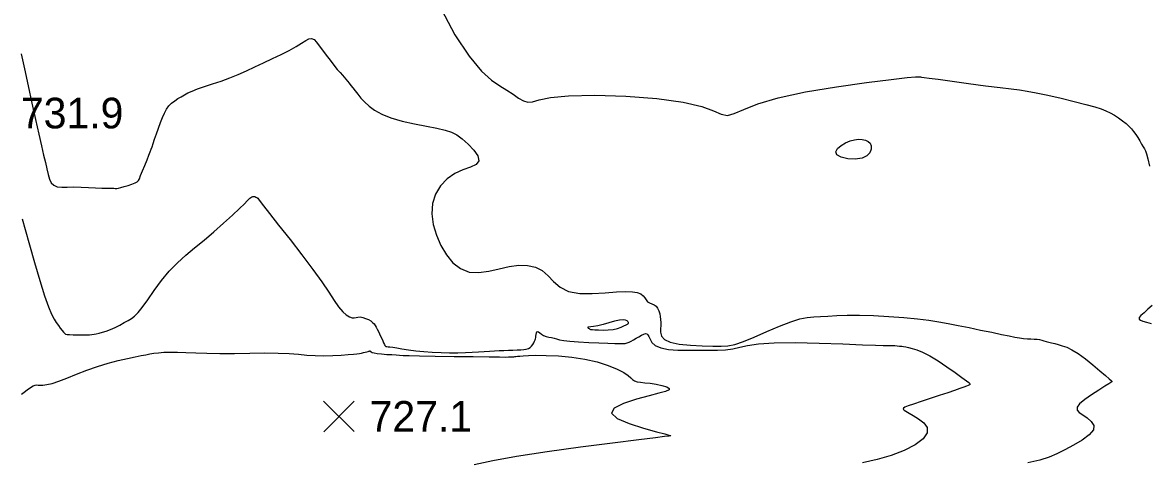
# Model space of a CAD drawing. Extents: x 2566142 to 2571431, y 418755 to 421584.
# Drawn here: x 2569092 to 2569643, y 420845 to 421060 of the extents above; entities that cross this region are included whole.
import ezdxf

# ---------------------------------------------------------------- set-up
doc = ezdxf.new("R2010")
doc.units = 0
for name, color, linetype in [('Contour_ADS_Major', 7, 'Continuous'), ('Contour_ADS_Minor', 7, 'Continuous'), ('Contour_ADS_Spot_Elevation', 7, 'Continuous')]:
    doc.layers.add(name, color=color, linetype=linetype)

# ---------------------------------------------------------------- blocks, each defined once
blk = doc.blocks.new('S750')
at = {"layer": 'Contour_ADS_Spot_Elevation'}
for p, q in [((-0.5, 0.498), (0.5, -0.498)), ((-0.498, -0.5), (0.498, 0.5))]:
    blk.add_line(p, q, dxfattribs=at)

msp = doc.modelspace()

# ---------------------------------------------------------------- linework, layer by layer
at = {"layer": 'Contour_ADS_Major'}
for points in [[(2569126.55, 420907.84), (2569127.66, 420908.08), (2569129.03, 420908.39), (2569130.67, 420908.82), (2569132.55, 420909.41), (2569134.63, 420910.2), (2569136.87, 420911.21), (2569139.15, 420912.36), (2569141.33, 420913.53), (2569143.27, 420914.62), (2569144.91, 420915.59), (2569146.43, 420916.72), (2569148.1, 420918.41), (2569150.17, 420921), (2569152.83, 420924.74), (2569156.01, 420929.27), (2569159.58, 420934.09), (2569163.39, 420938.72), (2569167.35, 420942.8), (2569171.46, 420946.48), (2569175.79, 420950.05), (2569180.39, 420953.83), (2569185.23, 420957.97), (2569189.99, 420962.21), (2569194.31, 420966.16), (2569197.78, 420969.4), (2569200.14, 420971.66), (2569201.58, 420973.08), (2569202.39, 420973.91), (2569202.89, 420974.4), (2569203.33, 420974.76), (2569203.77, 420975.02), (2569204.23, 420975.18), (2569204.72, 420975.22), (2569205.25, 420975.15), (2569205.8, 420974.97), (2569206.31, 420974.7), (2569206.74, 420974.35), (2569207.13, 420973.87), (2569207.88, 420972.8), (2569209.47, 420970.65), (2569212.39, 420966.87), (2569216.92, 420961.18), (2569222.49, 420954.19), (2569228.35, 420946.7), (2569233.74, 420939.56), (2569238.07, 420933.42), (2569241.43, 420928.37), (2569244.09, 420924.31), (2569246.3, 420921.18), (2569248.28, 420918.89), (2569250.06, 420917.32), (2569251.61, 420916.37), (2569252.9, 420915.93), (2569253.95, 420915.87), (2569254.85, 420916.03), (2569255.76, 420916.24), (2569256.8, 420916.3), (2569258.07, 420916.08), (2569259.46, 420915.63), (2569260.84, 420915.03), (2569262.03, 420914.34), (2569262.95, 420913.65), (2569263.62, 420912.93), (2569264.16, 420912.15), (2569264.66, 420911.28), (2569265.18, 420910.31), (2569265.73, 420909.25), (2569266.29, 420908.11), (2569266.85, 420906.94), (2569267.38, 420905.75), (2569267.88, 420904.63), (2569268.32, 420903.64), (2569268.68, 420902.85), (2569268.95, 420902.33), (2569269.19, 420902.03), (2569269.48, 420901.87), (2569269.89, 420901.8), (2569270.5, 420901.73), (2569271.42, 420901.63), (2569272.78, 420901.46), (2569274.71, 420901.17), (2569277.28, 420900.76), (2569280.42, 420900.26), (2569284.03, 420899.76), (2569287.98, 420899.33), (2569292.16, 420899.04), (2569296.44, 420898.87), (2569300.65, 420898.8), (2569304.65, 420898.82), (2569308.33, 420898.9), (2569311.69, 420899.03), (2569314.76, 420899.19), (2569317.57, 420899.36), (2569320.17, 420899.54), (2569322.6, 420899.7), (2569324.92, 420899.85), (2569327.19, 420899.96), (2569329.44, 420900.04), (2569331.61, 420900.11), (2569333.63, 420900.17)], [(2569091.39, 420964.38), (2569092.8, 420959.06), (2569094.87, 420951.59), (2569097.34, 420942.89), (2569099.92, 420934.17), (2569102.29, 420926.63), (2569104.2, 420921.2), (2569105.72, 420917.59), (2569106.95, 420915.24), (2569108.03, 420913.57), (2569109.06, 420912.11), (2569110.02, 420910.81), (2569110.86, 420909.72), (2569111.53, 420908.87), (2569112.05, 420908.3), (2569112.58, 420907.95), (2569113.35, 420907.76), (2569114.58, 420907.65), (2569116.4, 420907.57), (2569118.59, 420907.51), (2569120.85, 420907.49), (2569122.84, 420907.5), (2569124.36, 420907.56), (2569125.52, 420907.67), (2569126.55, 420907.84)], [(2569333.63, 420900.17), (2569335.42, 420900.25), (2569336.93, 420900.38), (2569338.18, 420900.59), (2569339.21, 420900.92), (2569340.07, 420901.4), (2569340.79, 420902.06), (2569341.39, 420902.84), (2569341.86, 420903.65), (2569342.23, 420904.41), (2569342.48, 420905.08), (2569342.66, 420905.68), (2569342.78, 420906.28), (2569342.88, 420906.96), (2569342.99, 420907.73), (2569343.15, 420908.47), (2569343.37, 420909.04), (2569343.71, 420909.26), (2569344.18, 420909.05), (2569344.81, 420908.51), (2569345.63, 420907.84), (2569346.64, 420907.21), (2569347.85, 420906.75), (2569349.19, 420906.44), (2569350.55, 420906.19), (2569351.84, 420905.92), (2569353.03, 420905.58), (2569354.44, 420905.18), (2569356.47, 420904.77), (2569359.49, 420904.39), (2569363.74, 420904.07), (2569368.71, 420903.81), (2569373.74, 420903.6), (2569378.16, 420903.44), (2569381.47, 420903.32), (2569383.79, 420903.25), (2569385.4, 420903.27), (2569386.58, 420903.38), (2569387.58, 420903.61), (2569388.53, 420903.97), (2569389.52, 420904.47), (2569390.63, 420905.1), (2569391.92, 420905.85), (2569393.3, 420906.64), (2569394.62, 420907.36), (2569395.76, 420907.89), (2569396.61, 420908.15), (2569397.23, 420908.06), (2569397.72, 420907.6), (2569398.19, 420906.71), (2569398.76, 420905.4), (2569399.71, 420903.88), (2569401.34, 420902.39), (2569403.97, 420901.18), (2569407.77, 420900.44), (2569412.44, 420900.09), (2569417.55, 420899.98), (2569422.66, 420899.98), (2569427.41, 420899.99), (2569431.75, 420900.05), (2569435.69, 420900.27), (2569439.27, 420900.74), (2569442.64, 420901.5), (2569446.55, 420902.38), (2569451.86, 420903.19), (2569459.46, 420903.7), (2569469.8, 420903.78), (2569481.6, 420903.52), (2569493.15, 420903.11), (2569502.76, 420902.72), (2569509.16, 420902.49), (2569512.86, 420902.4), (2569514.83, 420902.39), (2569516.03, 420902.39), (2569517.23, 420902.35), (2569518.53, 420902.28), (2569519.8, 420902.18), (2569520.96, 420902.07), (2569521.95, 420901.95), (2569522.89, 420901.8), (2569523.95, 420901.61), (2569525.29, 420901.34), (2569527.06, 420900.94), (2569529.35, 420900.27), (2569532.21, 420899.14), (2569535.71, 420897.35), (2569539.81, 420894.84), (2569544.13, 420891.94), (2569548.18, 420889.07), (2569551.47, 420886.67), (2569553.64, 420885.08), (2569554.85, 420884.17), (2569555.36, 420883.71), (2569555.47, 420883.49), (2569555.4, 420883.32), (2569555.12, 420883.11), (2569554.56, 420882.84), (2569553.66, 420882.47), (2569552.32, 420881.96), (2569550.43, 420881.28), (2569547.88, 420880.4)], [(2569547.88, 420880.4), (2569544.53, 420879.26), (2569540.37, 420877.89), (2569535.83, 420876.4), (2569531.44, 420874.95), (2569527.73, 420873.72), (2569525.11, 420872.81), (2569523.52, 420872.16), (2569522.77, 420871.68), (2569522.68, 420871.26), (2569523.11, 420870.78), (2569524.05, 420870.17), (2569525.55, 420869.32), (2569527.64, 420868.13), (2569530.24, 420866.54), (2569532.74, 420864.57), (2569534.39, 420862.25), (2569534.47, 420859.63), (2569532.42, 420856.76), (2569528.49, 420853.83), (2569523.14, 420851.02), (2569516.79, 420848.53), (2569509.9, 420846.52), (2569502.82, 420844.95)]]:
    msp.add_lwpolyline(points, dxfattribs=at)
at = {"layer": 'Contour_ADS_Minor'}
for points in [[(2569296.63, 421066.69), (2569303.23, 421054.3), (2569310.23, 421043.83), (2569316.25, 421036.59), (2569321.19, 421032.08), (2569325.26, 421029.31), (2569328.7, 421027.3), (2569331.7, 421025.3), (2569334.36, 421023.41), (2569336.74, 421021.97), (2569338.93, 421021.3), (2569341.18, 421021.61), (2569344.47, 421022.56), (2569349.97, 421023.7), (2569358.85, 421024.55), (2569371.71, 421024.75), (2569386.86, 421024.27), (2569402.04, 421023.14), (2569414.99, 421021.43), (2569424.04, 421019.27), (2569429.83, 421017.11), (2569433.61, 421015.48), (2569436.6, 421014.92), (2569439.98, 421015.79), (2569444.68, 421017.82), (2569451.58, 421020.55), (2569461.54, 421023.53), (2569474.93, 421026.38), (2569490.07, 421028.9), (2569504.76, 421030.99), (2569516.81, 421032.51), (2569524.59, 421033.4)], [(2569162.01, 421017.96), (2569163.18, 421019.58), (2569164.54, 421020.94), (2569166.05, 421022.09), (2569167.63, 421023.1), (2569169.21, 421024.03), (2569170.78, 421024.94), (2569172.49, 421025.86), (2569174.56, 421026.83), (2569177.21, 421027.87), (2569180.58, 421029.01), (2569184.5, 421030.27), (2569188.72, 421031.67), (2569193, 421033.21), (2569197.16, 421034.91), (2569201.24, 421036.73), (2569205.32, 421038.66), (2569209.51, 421040.67), (2569213.85, 421042.71), (2569218.13, 421044.74), (2569222.1, 421046.71), (2569225.5, 421048.57), (2569228.15, 421050.23), (2569230.16, 421051.57), (2569231.72, 421052.41), (2569233.02, 421052.59), (2569234.24, 421052.01), (2569235.47, 421050.76), (2569236.81, 421048.96), (2569238.36, 421046.78), (2569240.15, 421044.35), (2569242.07, 421041.86), (2569243.96, 421039.49), (2569245.65, 421037.43), (2569247.02, 421035.81), (2569248.11, 421034.57), (2569249.02, 421033.55), (2569249.83, 421032.64), (2569250.62, 421031.71), (2569251.43, 421030.71), (2569252.3, 421029.59), (2569253.26, 421028.31), (2569254.35, 421026.85), (2569255.63, 421025.21), (2569257.14, 421023.41), (2569258.96, 421021.49), (2569261.16, 421019.46), (2569263.92, 421017.42), (2569267.43, 421015.45), (2569271.89, 421013.66), (2569277.36, 421012.09), (2569283.36, 421010.76), (2569289.26, 421009.6), (2569294.42, 421008.6), (2569298.4, 421007.69), (2569301.48, 421006.67), (2569304.12, 421005.32), (2569306.77, 421003.43), (2569309.7, 421000.88), (2569312.47, 420997.96), (2569314.45, 420995.08), (2569314.98, 420992.64), (2569313.66, 420990.91), (2569310.86, 420989.59), (2569307.17, 420988.25), (2569303.18, 420986.44), (2569299.41, 420983.83), (2569296.17, 420980.43), (2569293.69, 420976.38), (2569292.21, 420971.77), (2569291.88, 420966.75), (2569292.59, 420961.51), (2569294.15, 420956.27), (2569296.36, 420951.26), (2569299.07, 420946.69), (2569302.26, 420942.82), (2569305.94, 420939.93), (2569310.13, 420938.27), (2569314.79, 420938), (2569319.76, 420938.71), (2569324.83, 420939.88), (2569329.8, 420940.99), (2569334.49, 420941.58), (2569338.79, 420941.5), (2569342.64, 420940.67), (2569345.97, 420938.99), (2569348.81, 420936.49), (2569351.56, 420933.61), (2569354.75, 420930.87), (2569358.9, 420928.83), (2569364.31, 420927.86), (2569370.5, 420927.74), (2569376.75, 420928.08), (2569382.37, 420928.52), (2569386.81, 420928.73), (2569390.13, 420928.66), (2569392.52, 420928.29), (2569394.18, 420927.64), (2569395.33, 420926.72), (2569396.15, 420925.67), (2569396.83, 420924.63)], [(2569090.8, 421045.09), (2569092.43, 421037.62), (2569094.22, 421029.37), (2569096.08, 421020.93), (2569097.87, 421012.87), (2569099.48, 421005.75), (2569100.8, 420999.99), (2569101.87, 420995.44), (2569102.73, 420991.79), (2569103.42, 420988.75), (2569104.03, 420986.07), (2569104.69, 420983.78), (2569105.56, 420981.96), (2569106.79, 420980.7), (2569108.52, 420980.03), (2569110.75, 420979.81), (2569113.45, 420979.82), (2569116.62, 420979.88), (2569120.16, 420979.83), (2569123.84, 420979.68), (2569127.33, 420979.49), (2569130.34, 420979.34), (2569132.64, 420979.26), (2569134.29, 420979.24), (2569135.46, 420979.24), (2569136.3, 420979.24), (2569136.96, 420979.21), (2569137.63, 420979.22), (2569138.47, 420979.32), (2569139.67, 420979.59), (2569141.32, 420980.06), (2569143.23, 420980.66), (2569145.09, 420981.31), (2569146.62, 420981.9), (2569147.62, 420982.4), (2569148.24, 420983), (2569148.74, 420983.94), (2569149.36, 420985.48), (2569150.27, 420987.74), (2569151.37, 420990.43), (2569152.48, 420993.15), (2569153.43, 420995.47), (2569154.09, 420997.13), (2569154.56, 420998.37), (2569154.98, 420999.57), (2569155.5, 421001.1), (2569156.22, 421003.24), (2569157.11, 421005.83), (2569158.09, 421008.63), (2569159.08, 421011.37), (2569160.03, 421013.86), (2569160.98, 421016.05), (2569162.01, 421017.96)], [(2569524.59, 421033.4), (2569528.76, 421033.78), (2569530.53, 421033.83), (2569531.13, 421033.75), (2569531.68, 421033.65), (2569532.9, 421033.5), (2569535.43, 421033.18), (2569539.89, 421032.59), (2569546.6, 421031.67), (2569554.67, 421030.56), (2569562.92, 421029.44), (2569570.14, 421028.5), (2569575.51, 421027.85), (2569579.61, 421027.35), (2569583.39, 421026.8), (2569587.8, 421025.98), (2569593.5, 421024.75), (2569599.99, 421023.25), (2569606.47, 421021.68), (2569612.16, 421020.24), (2569616.46, 421019.06), (2569619.59, 421018.08), (2569621.97, 421017.15), (2569624.02, 421016.15), (2569626.08, 421014.96), (2569628.13, 421013.64), (2569630.07, 421012.25), (2569631.79, 421010.89), (2569633.24, 421009.61), (2569634.46, 421008.34), (2569635.53, 421007.03), (2569636.54, 421005.6), (2569637.54, 421004.01), (2569638.52, 421002.38), (2569639.42, 421000.84), (2569640.2, 420999.55), (2569640.81, 420998.55), (2569641.34, 420997.52), (2569641.86, 420996.02), (2569642.47, 420993.61), (2569643.22, 420990.02)], [(2569396.83, 420924.63), (2569397.58, 420923.77), (2569398.52, 420923.19), (2569399.61, 420922.75), (2569400.7, 420922.28), (2569401.69, 420921.61), (2569402.47, 420920.6), (2569403.06, 420919.33), (2569403.47, 420917.91), (2569403.74, 420916.45), (2569403.9, 420915.04), (2569403.96, 420913.64), (2569403.96, 420912.17), (2569403.92, 420910.56), (2569403.94, 420908.79), (2569404.42, 420906.98), (2569405.82, 420905.31), (2569408.61, 420903.95), (2569413.05, 420903.02), (2569418.55, 420902.47), (2569424.28, 420902.17), (2569429.46, 420902.03), (2569433.51, 420901.98), (2569436.89, 420902.19), (2569440.3, 420902.88), (2569444.45, 420904.28), (2569449.8, 420906.49), (2569455.91, 420909.16), (2569462.09, 420911.82), (2569467.67, 420913.99), (2569472.13, 420915.35), (2569475.75, 420916.02), (2569478.96, 420916.3), (2569482.2, 420916.45), (2569485.88, 420916.68), (2569490.18, 420916.95), (2569495.25, 420917.15), (2569501.25, 420917.19), (2569508.2, 420916.98), (2569515.65, 420916.57), (2569523, 420916.01), (2569529.69, 420915.37), (2569535.31, 420914.69), (2569540.17, 420913.96), (2569544.76, 420913.13), (2569549.59, 420912.18), (2569554.97, 420911.08), (2569560.6, 420909.92), (2569566.03, 420908.8), (2569570.79, 420907.8), (2569574.54, 420907.01), (2569577.43, 420906.43), (2569579.71, 420906.02), (2569581.67, 420905.76), (2569583.5, 420905.62), (2569585.23, 420905.54), (2569586.82, 420905.48), (2569588.24, 420905.39), (2569589.46, 420905.21), (2569590.56, 420904.96), (2569591.62, 420904.67), (2569592.73, 420904.34), (2569593.97, 420904), (2569595.36, 420903.64), (2569596.91, 420903.25), (2569598.62, 420902.8), (2569600.54, 420902.26), (2569602.74, 420901.47), (2569605.31, 420900.24), (2569608.36, 420898.38), (2569611.91, 420895.82), (2569615.61, 420892.88), (2569619.04, 420890), (2569621.8, 420887.62), (2569623.57, 420886.06), (2569624.5, 420885.21), (2569624.86, 420884.83), (2569624.91, 420884.7), (2569624.81, 420884.59), (2569624.38, 420884.3), (2569623.34, 420883.64), (2569621.4, 420882.44), (2569618.43, 420880.57), (2569614.95, 420878.29), (2569611.61, 420875.92), (2569609.08, 420873.78), (2569607.88, 420872.11), (2569607.9, 420870.78), (2569608.9, 420869.61), (2569610.64, 420868.38), (2569612.79, 420866.92), (2569614.8, 420865.21), (2569616.01, 420863.25), (2569615.8, 420861.04), (2569613.75, 420858.61), (2569610.29, 420856.09), (2569606.11, 420853.63), (2569601.86, 420851.37), (2569598, 420849.43), (2569594.11, 420847.77), (2569589.56, 420846.3)], [(2569644.55, 420921.96), (2569642.5, 420920.04), (2569640.61, 420918.4), (2569639.12, 420917.05), (2569638.25, 420916), (2569638.17, 420915.23), (2569638.81, 420914.66), (2569640.09, 420914.18), (2569641.87, 420913.69), (2569644.08, 420913.09)], [(2569095.4, 420881.73), (2569096.74, 420882.57), (2569097.69, 420882.99), (2569098.4, 420883.09), (2569099.12, 420883.01), (2569100.07, 420882.92), (2569101.45, 420882.95), (2569103.39, 420883.22), (2569105.96, 420883.82), (2569109.25, 420884.87), (2569113.29, 420886.4), (2569117.93, 420888.26), (2569122.96, 420890.23), (2569128.19, 420892.08), (2569133.4, 420893.65), (2569138.37, 420894.93), (2569142.86, 420895.96), (2569146.65, 420896.76), (2569149.59, 420897.38), (2569151.89, 420897.85), (2569153.89, 420898.22), (2569155.88, 420898.52), (2569158.14, 420898.79), (2569160.77, 420899.01), (2569163.83, 420899.13), (2569167.4, 420899.12), (2569171.53, 420898.98), (2569176.31, 420898.76), (2569181.84, 420898.55), (2569188.19, 420898.44), (2569195.36, 420898.49), (2569202.89, 420898.61), (2569210.21, 420898.7), (2569216.76, 420898.66), (2569222.15, 420898.41), (2569226.65, 420898.04), (2569230.7, 420897.66), (2569234.74, 420897.39), (2569239.08, 420897.33), (2569243.47, 420897.43), (2569247.57, 420897.63), (2569251.01, 420897.87), (2569253.53, 420898.08), (2569255.28, 420898.26), (2569256.53, 420898.44), (2569257.51, 420898.63), (2569258.45, 420898.84), (2569259.34, 420899.05), (2569260.11, 420899.25), (2569260.73, 420899.42), (2569261.13, 420899.55), (2569261.37, 420899.65), (2569261.5, 420899.7), (2569261.56, 420899.73), (2569261.6, 420899.72), (2569261.63, 420899.7), (2569261.66, 420899.67), (2569261.68, 420899.63), (2569261.69, 420899.6), (2569261.73, 420899.55), (2569261.82, 420899.48), (2569261.98, 420899.35), (2569262.25, 420899.17), (2569262.78, 420898.94), (2569263.72, 420898.69), (2569265.22, 420898.44), (2569267.36, 420898.22), (2569269.86, 420898.02), (2569272.34, 420897.86), (2569274.45, 420897.73), (2569276.03, 420897.62), (2569277.83, 420897.53), (2569280.78, 420897.43), (2569285.85, 420897.32), (2569293.57, 420897.18), (2569302.84, 420897.03), (2569312.14, 420896.89), (2569319.94, 420896.78), (2569325.11, 420896.72), (2569328.02, 420896.7), (2569329.4, 420896.72), (2569330, 420896.75), (2569330.44, 420896.78), (2569330.86, 420896.8), (2569331.25, 420896.83), (2569331.64, 420896.85), (2569332.03, 420896.86), (2569332.5, 420896.89), (2569333.09, 420896.95), (2569333.89, 420897.05), (2569334.99, 420897.2), (2569336.65, 420897.36), (2569339.19, 420897.5), (2569342.88, 420897.57), (2569347.91, 420897.51), (2569353.92, 420897.23), (2569360.4, 420896.65), (2569366.87, 420895.69), (2569372.88, 420894.28), (2569378.19, 420892.59), (2569382.6, 420890.79)], [(2569382.6, 420890.79), (2569385.92, 420889.1), (2569388.05, 420887.67), (2569389.34, 420886.52), (2569390.21, 420885.64), (2569391.1, 420885.02), (2569392.38, 420884.63), (2569394.1, 420884.38), (2569396.26, 420884.15), (2569398.84, 420883.84), (2569401.76, 420883.36), (2569404.6, 420882.74), (2569406.91, 420882.05), (2569408.19, 420881.34), (2569408.05, 420880.66), (2569406.37, 420879.9), (2569403.13, 420878.96), (2569398.28, 420877.71), (2569392.06, 420876.06), (2569385.83, 420874.05), (2569381.2, 420871.77), (2569379.82, 420869.28), (2569382.7, 420866.68), (2569388.58, 420864.17), (2569395.59, 420861.93), (2569401.85, 420860.19), (2569405.92, 420859.09), (2569408.03, 420858.5), (2569408.8, 420858.27), (2569408.89, 420858.21), (2569408.84, 420858.18), (2569408.75, 420858.15), (2569408.65, 420858.13), (2569408.54, 420858.12), (2569408.44, 420858.1), (2569408.33, 420858.09), (2569408.2, 420858.08), (2569408.02, 420858.05), (2569407.58, 420857.99), (2569405.81, 420857.76), (2569401.44, 420857.21), (2569393.21, 420856.19), (2569380.42, 420854.61), (2569364.72, 420852.6), (2569348.32, 420850.36), (2569333.43, 420848.1), (2569321.72, 420845.98), (2569312.69, 420844.01)], [(2569091.02, 420878.53), (2569092.3, 420879.5), (2569093.84, 420880.64), (2569095.4, 420881.73)], [(2569589.56, 420846.3), (2569583.72, 420844.96)]]:
    msp.add_lwpolyline(points, dxfattribs=at)
for points in [[(2569494.46, 421001.53), (2569496.69, 421002.47), (2569498.84, 421003.02), (2569500.85, 421003.24), (2569502.68, 421003.16), (2569504.27, 421002.82), (2569505.57, 421002.21), (2569506.5, 421001.27), (2569507, 420999.98), (2569506.99, 420998.36), (2569506.34, 420996.63), (2569504.91, 420995.07), (2569502.54, 420993.96), (2569499.23, 420993.51), (2569495.58, 420993.7), (2569492.31, 420994.42), (2569490.15, 420995.57), (2569489.64, 420997.03), (2569490.5, 420998.64), (2569492.26, 421000.21), (2569494.46, 421001.53)], [(2569383.85, 420914.74), (2569381.43, 420914.23), (2569378.63, 420913.48), (2569375.76, 420912.69), (2569373.18, 420912.03), (2569371.15, 420911.64), (2569369.7, 420911.45), (2569368.77, 420911.37), (2569368.32, 420911.28), (2569368.28, 420911.1), (2569368.53, 420910.85), (2569368.92, 420910.6), (2569369.3, 420910.38), (2569369.59, 420910.24), (2569369.95, 420910.15), (2569370.6, 420910.1), (2569371.75, 420910.03), (2569373.54, 420909.94), (2569375.79, 420909.89), (2569378.24, 420909.95), (2569380.64, 420910.2), (2569382.77, 420910.68), (2569384.56, 420911.3), (2569385.99, 420911.94), (2569387.03, 420912.49), (2569387.68, 420912.84), (2569388.02, 420913.03), (2569388.16, 420913.14), (2569388.2, 420913.23), (2569388.22, 420913.36), (2569388.21, 420913.54), (2569388.11, 420913.78), (2569387.89, 420914.09), (2569387.49, 420914.45), (2569386.77, 420914.76), (2569385.61, 420914.89), (2569383.85, 420914.74)]]:
    msp.add_lwpolyline(points, close=True, dxfattribs=at)

# ---------------------------------------------------------------- block references
at = {"layer": 'Contour_ADS_Spot_Elevation', "xscale": 15, "yscale": 15}
msp.add_blockref('S750', (2569246.46, 420867.68), dxfattribs=at)

# ---------------------------------------------------------------- texts
at = {"layer": 'Contour_ADS_Spot_Elevation'}
for s, p in [('731.9', (2569090.72, 421008.54)), ('727.1', (2569261.46, 420860.18))]:
    msp.add_text(s, height=15, dxfattribs=at).set_placement(p)

doc.saveas('drawing.dxf')
